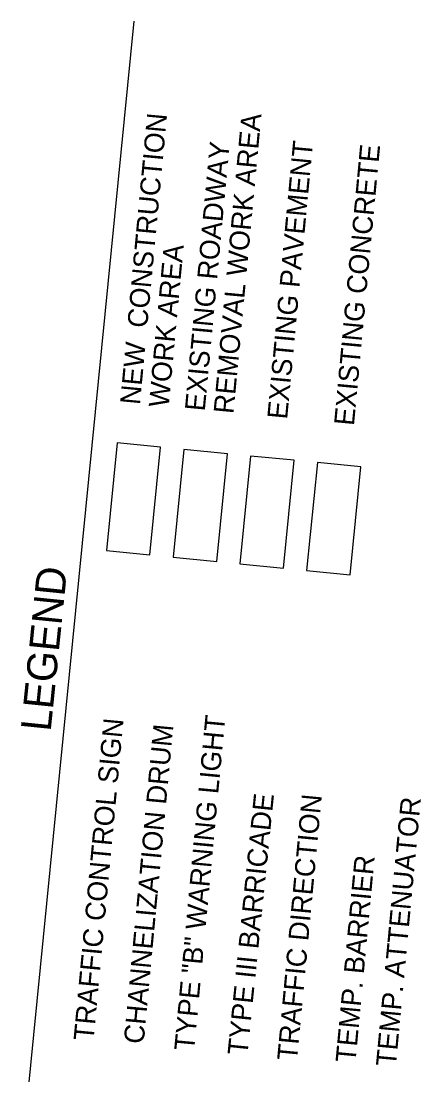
# Model space of a CAD drawing. Extents: x 1795987 to 1799689, y 243690 to 251545.
# Drawn here: x 1797817.6 to 1797973.5, y 245475.6 to 245887 of the extents above; entities that cross this region are included whole.
import ezdxf

# ---------------------------------------------------------------- set-up
doc = ezdxf.new("R2010")
doc.units = 0
for name, color, linetype in [('LEGEND', 7, 'Continuous'), ('Level 2', 7, 'Continuous'), ('Level 62', 7, 'Continuous'), ('Phase 2 Hatching', 7, 'Continuous')]:
    doc.layers.add(name, color=color, linetype=linetype)

msp = doc.modelspace()

# ---------------------------------------------------------------- linework, layer by layer
at = {"layer": 'LEGEND'}
msp.add_line((1797817.74, 245443.45), (1797861.68, 245886.96), dxfattribs=at)
for points in [[(1797867.8, 245678.59), (1797871.97, 245720.66), (1797854.98, 245722.34), (1797850.81, 245680.28)], [(1797893.84, 245676.01), (1797898, 245718.08), (1797881.02, 245719.76), (1797876.85, 245677.7)], [(1797919.87, 245673.43), (1797924.04, 245715.5), (1797907.05, 245717.18), (1797902.88, 245675.12)], [(1797945.91, 245670.85), (1797950.08, 245712.92), (1797933.09, 245714.61), (1797928.92, 245672.54)]]:
    msp.add_lwpolyline(points, close=True, dxfattribs=at)
at = {"layer": 'Level 2'}
msp.add_lwpolyline([(1797945.91, 245670.85), (1797950.08, 245712.92), (1797933.09, 245714.61), (1797928.92, 245672.54)], close=True, dxfattribs=at)
at = {"layer": 'Level 62'}
msp.add_lwpolyline([(1797919.87, 245673.43), (1797924.04, 245715.5), (1797907.05, 245717.18), (1797902.88, 245675.12), (1797919.87, 245673.43)], dxfattribs=at)
at = {"layer": 'Phase 2 Hatching'}
msp.add_lwpolyline([(1797945.91, 245670.85), (1797950.08, 245712.92), (1797933.09, 245714.61), (1797928.92, 245672.54)], close=True, dxfattribs=at)

# ---------------------------------------------------------------- texts
at = {"layer": 'LEGEND'}
for s, height, rotation, p in [('NEW  CONSTRUCTION', 7.7999, 84.6544, (1797863.89, 245736.99)), ('REMOVAL WORK AREA', 7.7999, 84.6544, (1797900.36, 245733.44)), ('EXISTING ROADWAY', 7.7999, 84.6544, (1797889.17, 245734.48)), ('EXISTING PAVEMENT', 7.7999, 84.6544, (1797921.3, 245731.32)), ('EXISTING CONCRETE', 7.7999, 84.6544, (1797947.35, 245728.82)), ('WORK AREA', 7.8, 84.6544, (1797875.08, 245735.94)), ('LEGEND', 11.7, 84.1754, (1797829.06, 245609.39)), ('TYPE "B" WARNING LIGHT', 7.7999, 84.6544, (1797885.02, 245484.78)), ('TRAFFIC CONTROL SIGN', 7.7999, 84.6544, (1797845.77, 245488.67)), ('CHANNELIZATION DRUM', 7.7999, 84.6544, (1797865.33, 245487.48)), ('TYPE III BARRICADE', 7.7999, 84.1754, (1797905.8, 245483.02)), ('TRAFFIC DIRECTION', 7.7999, 84.6544, (1797925.16, 245480.94)), ('TEMP. ATTENUATOR', 7.7999, 84.6544, (1797963.7, 245478.67)), ('TEMP. BARRIER', 7.7999, 84.6544, (1797947.94, 245480.17))]:
    msp.add_text(s, height=height, rotation=rotation, dxfattribs=at).set_placement(p)

doc.saveas('drawing.dxf')
